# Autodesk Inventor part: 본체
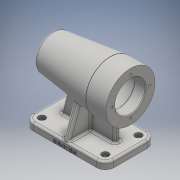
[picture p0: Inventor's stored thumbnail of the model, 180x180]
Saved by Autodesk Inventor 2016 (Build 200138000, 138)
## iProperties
Created: 2018-09
Part Number: 본체
Material: 일반
Document SubType Name: Modeling
Designer: 3sil_cad018
Density: 1 g/cm^3
Appearance: 기본값
Author: 3sil_cad018
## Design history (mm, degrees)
sketch "스케치1"
  geometry: L1 (0, 0)-(112, 0); L2 (112, 0)-(112, 34); L3 (112, 34)-(84, 34); L4 (3.73, 24.144)-(84, 34); L5 (6, 0)-(6, 10.5); L6 (6, 10.5)-(9, 10.5); L7 (9, 10.5)-(9, 16); L8 (9, 16)-(13, 16); L9 (13, 16)-(13, 17.5); L10 (13, 17.5)-(31, 17.5); L11 (31, 17.5)-(31, 21); L12 (31, 21)-(43, 21); L13 (43, 21)-(43, 24); L14 (43, 24)-(97, 24); L15 (97, 24)-(97, 21); L16 (97, 21)-(112, 21); L17 (112, 0)-(6, 0); A1 r 80 centre (80, 0) between (3.73, 24.144) and (0, 0)
  constraints: 34 end point, 11 perpendicular, 3 point on line, 3 vertical, 2 point on circle, 1 centre point, 1 horizontal, 1 parallel
  dimensions: "d0" = 112 distance from line of L2 L1.start; "d1" = 28 distance of L2.end L3.end; "d2" = 68 diameter of L3 L1; "d3" = 7 deg angle of L3 L4; "d4" = 80 radius of A1; "d6" = 42 diameter of L16 L1; "d7" = 15 distance of L15.end L16.end; "d8" = 48 diameter of L14 L1; "d9" = 42 diameter of L12 L1; "d10" = 35 diameter of L10 L1; "d11" = 32 diameter of L8 L17; "d12" = 21 diameter of L6 L17; "d13" = 54 distance of L13.end L14.end; "d14" = 18 distance of L9.end L10.end; "d15" = 3 distance of L5.end L6.end; "d16" = 4 distance of L7.end L8.end; "d17" = 12 distance of L11.end L12.end
revolve "회전1" stored, may be unused: angle "d5" = 90 deg
revolve "회전2" stored, may be unused: angle "d18" = 90 deg
sketch "스케치2"
  geometry: A1 r 26 centre (0, 0) between (-26, 0) and (26, 0); 3 further points
  constraints: 4 point on circle, 1 centre point, 1 coincident
  dimensions: "d19" = 52 diameter of A1
hole "구멍1" sketch "스케치2" at (-26, 0), (26, 0), (0, 26), (0, -26) diameter "d24" = 3.242; stored, may be unused: countersink angle "d28" = 90 deg, drill point angle "d30" = 118 deg; dims "d25" = 8, "d26" = 4, "d27" = 2, "d29" = 11
fillet "모깎기1" dims "d31" = 3
fillet "모깎기2" dims "d32" = 3
chamfer "모따기1" distance "d33" = 1; stored, may be unused: second distance "d34" = 2, angle "d35" = 45 deg
node "작업 평면1"
sketch "스케치3"
  geometry: L1 (0, 35)-(112, 35); L2 (112, 35)-(112, -35); L3 (112, -35)-(0, -35); L4 (0, -35)-(0, 35); L5 (112, -34)-(112, 34) reference; 2 further points
  constraints: 8 end point, 2 parallel, 1 collinear, 1 horizontal, 1 horizontal alignment, 1 midpoint, 1 perpendicular
  dimensions: "d37" = 112 distance of L1.start L1.end; "d38" = 70 distance of L3.end L1.start
extrude "돌출1" join sketch "스케치3" distance "d39" = 10; taper "d40" = 0 deg
fillet "모깎기3" dims "d41" = 0.3
fillet "모깎기4" dims "d42" = 12
fillet "모깎기5" dims "d43" = 3
sketch "스케치4"
  geometry: L1 (12, 35)-(100, 35) reference; L2 (112, 23)-(112, -23) reference; L3 (100, -35)-(12, -35) reference; L4 (0, -23)-(0, 23) reference; A1 r 12 centre (12, 23) between (12, 35) and (0, 23) reference; A2 r 12 centre (100, 23) between (112, 23) and (100, 35) reference; A3 r 12 centre (100, -23) between (100, -35) and (112, -23) reference; A4 r 12 centre (12, -23) between (0, -23) and (12, -35) reference; 1 further point
hole "구멍2" sketch "스케치4" at (12, 23), (100, 23), (100, -23), (12, -23) diameter "d44" = 5.5; stored, may be unused: countersink angle "d48" = 90 deg, drill point angle "d50" = 118 deg; dims "d45" = 8, "d46" = 9.5, "d47" = 5.4, "d49" = 11
sketch "스케치5"
  geometry: L1 (-100, -64)-(-12, -64) reference; L2 (-5.669, -24.382)-(-84, -34) reference; L3 (-18, -68.54)-(-29.432, -25.874); L4 (-29.432, -25.874)-(-94, -29.757); L5 (-94, -29.757)-(-94, -68.54); L6 (-84, 34)-(-84, -34) reference; L7 (-94, -68.54)-(-18, -68.54); L8 (-112, -67)-(-112, -74) reference; L9 (0, -74)-(0, -67) reference; L10 (-100, -67)-(-12, -67) reference; L11 (-100, -74)-(-100, -67) reference; L12 (-12, -74)-(-100, -74) reference; L13 (-12, -67)-(-12, -74) reference; 1 further point
  constraints: 8 end point, 1 parallel, 1 perpendicular
  dimensions: "d51" = 18 distance between parallel lines of L8 L5; "d52" = 105 deg angle of L3 L1; "d53" = 18 distance from line of L3.start L9
extrude "돌출2" join sketch "스케치5" stored distance "d54" = 8; taper "d55" = 0 deg
node "작업 평면2"
sketch "스케치6"
  geometry: L1 (10, 0)-(10, 46) reference; L2 (47.031, 23)-(7, 23); L3 (7, 23)-(7, -12); L4 (7, -12)-(52.198, 4.451); L5 (52.198, 4.451)-(47.031, 23); L6 (0, -12)-(7, -12) reference; L7 (10, 46)-(10, 0); L8 (7, 23)-(7, 58); L9 (7, 58)-(52.198, 41.549); L10 (52.198, 41.549)-(47.031, 23); L11 (40.236, 27)-(47.031, 27) reference; L12 (47.031, 19)-(40.236, 19) reference; C1 r 24.382 at (74, 23) reference; A1 r 34 centre (74, 23) between (40.236, 19) and (40.236, 27) reference; A2 r 3 centre (7, -9) between (7, -12) and (10, -9) reference; A3 r 3 centre (7, 55) between (10, 55) and (7, 58); 3 further points; 1 other entity
  constraints: 16 end point, 6 symmetric about line, 2 point on circle, 1 centre point, 1 horizontal alignment, 1 midpoint, 1 perpendicular, 2 other
extrude "돌출3" join sketch "스케치6" stored distance "d57" = 8; taper "d58" = 0 deg
sketch "스케치8"
  geometry: L1 (100, 0)-(100, 7) reference; L2 (100, 0)-(88, 0) reference; 2 further points
  constraints: 1 other
  dimensions: "d62" = 56 distance from line of L1 point (44, 3); "d63" = 3 distance from line of L2 point (44, 3)
feature "엠보싱1" sketch "스케치8" dims "d0" = 112, "d1" = 28, "d2" = 68, "d3" = 7 deg, "d4" = 80, "d6" = 42, "d7" = 15, "d8" = 48, "d9" = 42, "d10" = 35, "d11" = 32, "d12" = 21, "d13" = 54, "d14" = 18, "d15" = 3, "d16" = 4, "d17" = 12, "d64" = 0.5, "d65" = 0
fillet "모깎기9" dims "d66" = 3
fillet "모깎기10" dims "d67" = 3
fillet "모깎기11" dims "d68" = 3
node "솔리드1"
node "투영된 루프1"
node "투영된 루프2"
node "투영된 루프3"
other parameters: "d20" = 0.5, "d21" = 2, "d22" = 0, "d36" = -74
